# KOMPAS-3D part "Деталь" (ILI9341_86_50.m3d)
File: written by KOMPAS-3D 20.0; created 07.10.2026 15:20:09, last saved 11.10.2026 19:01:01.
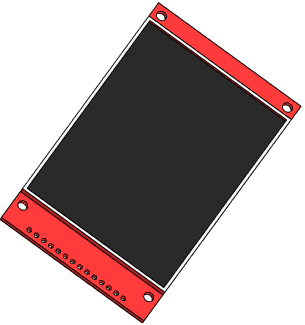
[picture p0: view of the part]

Document properties: Полное имя файла: D:\myProjects\Progect_esp32\box_compas\монитор\ILI9341_86_50.m3d

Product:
- Part/product: Деталь
    Масса: 0.0790697

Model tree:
1. Эскиз:1
2. Элемент выдавливания:1
     Расстояние 1 = 1.5
3. Эскиз:2  (with: Элемент выдавливания:1)
4. Элемент выдавливания:2
     Расстояние 1 = 2
5. Эскиз:3  (with: Элемент выдавливания:1)
6. Элемент выдавливания:3
     Расстояние 2 = 3.5
7. Массив по сетке:1  (with: Элемент выдавливания:3, Эскиз:3, Элемент выдавливания:1)  (4 pattern instances)
     Шаг 1 = 44.2; Угол раствора = 90; Шаг 2 = 75.9
8. Эскиз:5  (with: Элемент выдавливания:1)
9. Элемент выдавливания:4
     Расстояние 2 = 3.5
10. Массив по сетке:2  (with: Элемент выдавливания:4, Эскиз:5)  (14 pattern instances)
     Шаг 1 = 10; Угол раствора = -90; Шаг 2 = 2.54; Геометрический массив = 128
11. Эскиз:6  (with: Элемент выдавливания:1, Элемент выдавливания:4)
12. Эскиз:7  (with: Элемент выдавливания:2)
13. Элемент выдавливания:5
     Расстояние 2 = 0.5
14. Элемент выдавливания:6  (with: Элемент выдавливания:5)
     Расстояние 2 = 0.5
